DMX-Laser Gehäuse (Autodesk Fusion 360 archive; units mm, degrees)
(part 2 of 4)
sketch "Skizze2" plane through (0, 0, 5) normal (0, 0, 1) x axis (-1, 0, 0)
  line L1 (-37, -30) -> (-28, -30)
  line L2 (-40, -42) -> (-40, -33)
  line L3 (22, -45) -> (-37, -45)
  line L4 (25, 2) -> (25, -42)
  line L5 (-2, 5) -> (22, 5)
  line L6 (-5, 42) -> (-5, 8)
  line L7 (-22, 45) -> (-8, 45)
  line L8 (-25, -27) -> (-25, 42)
  line L9 (-20, -13) -> (-20, -45)
  line L10 (25, -13) -> (-25, -13)
  circle C1 centre (20, 0) radius 1.75
  circle C2 centre (20, -40) radius 1.75
  circle C3 centre (-20, 0) radius 1.75
  circle C4 centre (-10, 40) radius 1.75
  circle C5 centre (-20, 40) radius 1.75
  circle C6 centre (-35, -37.5) radius 1.75
  arc A1 centre (-37, -33) radius 3 clockwise from (-40, -33) to (-37, -30)
  arc A2 centre (-37, -42) radius 3 clockwise from (-37, -45) to (-40, -42)
  arc A3 centre (22, -42) radius 3 clockwise from (25, -42) to (22, -45)
  arc A4 centre (22, 2) radius 3 clockwise from (22, 5) to (25, 2)
  arc A5 centre (-2, 8) radius 3 clockwise from (-2, 5) to (-5, 8)
  arc A6 centre (-8, 42) radius 3 clockwise from (-8, 45) to (-5, 42)
  arc A7 centre (-22, 42) radius 3 clockwise from (-25, 42) to (-22, 45)
  arc A8 centre (-28, -27) radius 3 clockwise from (-25, -27) to (-28, -30)
  point P32 (-20, -45)
  point P34 (-25, -13)
  point P35 (25, -13)
  point P33 (-20, -13)
  coincident L3 P32
  perpendicular L3 L9
  coincident L8 P34
  coincident L4 P35
  perpendicular L4 L10
  dimension "d3" distance P32 P33 = 32
sketch "Skizze3" plane through (0, 0, 0) normal (0, 0, 1) x axis (1, 0, 0)
  line L1 (-25, 13) -> (25, 13)
  line L2 (-25, 23) -> (-25, 13)
  line L3 (25, 23) -> (-25, 23)
  line L4 (25, 13) -> (25, 23)
  line L5 (-25, 13) -> (25, 13)
  line L6 (-25, 3) -> (-25, 13)
  line L7 (25, 3) -> (-25, 3)
  line L8 (25, 13) -> (25, 3)
  point P2 (25, 13)
  point P3 (-25, 13)
  point P5 (25, 23)
  point P8 (25, 3)
  horizontal L1
  vertical L2
  horizontal L3
  vertical L4
  horizontal L5
  vertical L6
  horizontal L7
  vertical L8
  dimension "d4" distance P2 P3 = 50
  dimension "d5" distance P2 P5 = 10
  dimension "d6" distance P2 P8 = 10
sketch "Skizze4" plane through (0, 0, 5) normal (0, 0, 1) x axis (-1, 0, 0)
  line L1 (-37, -30) -> (-28, -30)
  line L2 (-40, -42) -> (-40, -33)
  line L3 (22, -45) -> (-37, -45)
  line L4 (25, 2) -> (25, -42)
  line L5 (-2, 5) -> (22, 5)
  line L6 (-5, 42) -> (-5, 8)
  line L7 (-22, 45) -> (-8, 45)
  line L8 (-25, -27) -> (-25, 42)
  line L9 (25, -3) -> (-25, -3)
  line L10 (25, -23) -> (25, -3)
  line L11 (-25, -23) -> (25, -23)
  line L12 (-25, -3) -> (-25, -23)
  line L13 (5, -3) -> (-25, -3)
  line L14 (5, -23) -> (5, -3)
  circle C1 centre (20, 0) radius 1.75
  circle C2 centre (20, -40) radius 1.75
  circle C3 centre (-20, 0) radius 1.75
  circle C4 centre (-10, 40) radius 1.75
  circle C5 centre (-20, 40) radius 1.75
  circle C6 centre (-35, -37.5) radius 1.75
  arc A1 centre (-37, -33) radius 3 clockwise from (-40, -33) to (-37, -30)
  arc A2 centre (-37, -42) radius 3 clockwise from (-37, -45) to (-40, -42)
  arc A3 centre (22, -42) radius 3 clockwise from (25, -42) to (22, -45)
  arc A4 centre (22, 2) radius 3 clockwise from (22, 5) to (25, 2)
  arc A5 centre (-2, 8) radius 3 clockwise from (-2, 5) to (-5, 8)
  arc A6 centre (-8, 42) radius 3 clockwise from (-8, 45) to (-5, 42)
  arc A7 centre (-22, 42) radius 3 clockwise from (-25, 42) to (-22, 45)
  arc A8 centre (-28, -27) radius 3 clockwise from (-25, -27) to (-28, -30)
  point P32 (-25, -3)
  point P37 (5, -23)
  point P35 (-25, -23)
  point P36 (5, -3)
  horizontal L9
  vertical L10
  horizontal L11
  vertical L12
  coincident L8 P32
  perpendicular L12 L13
  coincident L11 P37
  perpendicular L11 L14
  dimension "d7" distance P32 P35 = 20
  dimension "d8" distance P32 P36 = 30
extrude "Extrusion2" add sketch "Skizze4" profile of L8 L9 L11 L12 L13 L14 along normal blind 44.55
sketch "Skizze5" plane through (25, 0, 0) normal (1, 0, 0) x axis (0, 1, 0)
  line L1 (27, 0) -> (-42, 0)
  line L2 (27, 5) -> (27, 0)
  line L3 (23, 5) -> (27, 5)
  line L4 (23, 49.55) -> (23, 5)
  line L5 (3, 49.55) -> (23, 49.55)
  line L6 (3, 5) -> (3, 49.55)
  line L7 (-42, 5) -> (3, 5)
  line L8 (-42, 0) -> (-42, 5)
  line L9 (3, 39.55) -> (3, 5)
  line L10 (13, 39.55) -> (3, 39.55)
  line L11 (13, 37.7147) -> (3, 37.7147)
  circle C1 centre (13, 39.55) radius 2.5
  point P8 (3, 5)
  point P10 (3, 5)
  point P13 (3, 37.7147)
  point P12 (13, 39.55)
  point P15 (13, 39.55)
  point P11 (3, 39.55)
  coincident P8 P10
  perpendicular L7 L9
  perpendicular L6 L10
  coincident L6 P13
  perpendicular L6 L11
  coincident P12 P15
  dimension "d11" distance P10 P11 = 34.55
  dimension "d12" distance P11 P12 = 10
  dimension "d13" diameter C1 = 5
extrude "Extrusion3" cut sketch "Skizze5" profile of C1 against normal blind 50
extrude "Extrusion4" new body sketch "Skizze5" profile of L6 L9 L10 L11 C1 along normal blind 5
split "Teilen1"
sketch "Skizze6" plane through (0, 0, 5) normal (0, 0, 1) x axis (-1, 0, 0)
  line L1 (-25, -23) -> (5, -23)
  line L2 (-25, -27) -> (-25, -23)
  line L3 (-37, -30) -> (-28, -30)
  line L4 (-40, -42) -> (-40, -33)
  line L5 (22, -45) -> (-37, -45)
  line L6 (25, 2) -> (25, -42)
  line L7 (-2, 5) -> (22, 5)
  line L8 (-5, 42) -> (-5, 8)
  line L9 (-22, 45) -> (-8, 45)
  line L10 (-25, -3) -> (-25, 42)
  line L11 (5, -3) -> (-25, -3)
  line L12 (5, -23) -> (5, -3)
  arc A1 centre (-28, -27) radius 3 clockwise from (-25, -27) to (-28, -30)
  arc A2 centre (-37, -33) radius 3 clockwise from (-40, -33) to (-37, -30)
  arc A3 centre (-37, -42) radius 3 clockwise from (-37, -45) to (-40, -42)
  arc A4 centre (22, -42) radius 3 clockwise from (25, -42) to (22, -45)
  arc A5 centre (22, 2) radius 3 clockwise from (22, 5) to (25, 2)
  arc A6 centre (-2, 8) radius 3 clockwise from (-2, 5) to (-5, 8)
  arc A7 centre (-8, 42) radius 3 clockwise from (-8, 45) to (-5, 42)
  arc A8 centre (-22, 42) radius 3 clockwise from (-25, 42) to (-22, 45)
  circle C1 centre (20, 0) radius 1.75
  circle C2 centre (20, -40) radius 1.75
  circle C3 centre (-20, 0) radius 1.75
  circle C4 centre (-10, 40) radius 1.75
  circle C5 centre (-20, 40) radius 1.75
  circle C6 centre (-35, -37.5) radius 1.75
  circle C7 centre (-20, 0) radius 4.5
  concentric C3 C7
  dimension "d18" diameter C7 = 9
extrude "Extrusion5" cut sketch "Skizze6" profile of L11 C3 C7 along normal blind 5
fillet "Abrundung1" radius 5
fillet "Abrundung2" radius 5
sketch "Skizze7" plane through (0, 0, 49.55) normal (0, 0, 1) x axis (-1, 0, 0)
  line L1 (-25, -3) -> (5, -3)
  line L2 (-25, -23) -> (-25, -3)
  line L3 (5, -23) -> (-25, -23)
  line L4 (5, -3) -> (5, -23)
  line L5 (-25, -17) -> (-22, -17)
  line L6 (-1, -3) -> (-1, -6)
  line L7 (5, -9) -> (2, -9)
  circle C1 centre (-22, -20) radius 1.6
  circle C2 centre (-22, -20) radius 3
  circle C3 centre (2, -6) radius 1.6
  circle C4 centre (2, -6) radius 3
  point P10 (-22, -17)
  point P11 (-25, -17)
  point P12 (-1, -6)
  point P13 (-1, -3)
  point P14 (2, -9)
  point P15 (5, -9)
  concentric C1 C2
  concentric C3 C4
  tangent L4 C4
  coincident C2 P10
  coincident L2 P11
  tangent C2 L5
  perpendicular L2 L5
  coincident C4 P12
  coincident L1 P13
  perpendicular L1 L6
  coincident C4 P14
  coincident L4 P15
  perpendicular L4 L7
  dimension "d27" diameter C1 = 3.2
  dimension "d28" diameter C3 = 3.2
fillet "Abrundung3" radius 4
extrude "Extrusion6" cut sketch "Skizze7" profile of C1 C3 against normal blind 32
extrude "Extrusion7" cut sketch "Skizze7" profile of L1 L2 L3 L4 C1 C2 C3 C4 L5 L7 against normal blind 3
sketch "Skizze8" plane through (0, 0, 5) normal (0, 0, 1) x axis (-1, 0, 0)
  line L1 (-25.1716, -28) -> (5, -28)
  line L2 (-37, -30) -> (-28, -30)
  line L3 (-40, -42) -> (-40, -33)
  line L4 (22, -45) -> (-37, -45)
  line L5 (25, 2) -> (25, -42)
  line L6 (-2, 5) -> (22, 5)
  line L7 (-5, 42) -> (-5, 8)
  line L8 (-22, 45) -> (-8, 45)
  line L9 (-25, 2) -> (-25, 42)
  line L10 (-24.0311, 2) -> (-25, 2)
  line L11 (5, 2) -> (-15.9689, 2)
  line L12 (5, -28) -> (5, 2)
  line L13 (-10, 10) -> (-5, 10)
  line L14 (-12, 27) -> (-12, 12)
  line L15 (-5, 29) -> (-10, 29)
  arc A1 centre (-28, -27) radius 3 clockwise from (-25.1716, -28) to (-28, -30)
  arc A2 centre (-37, -33) radius 3 clockwise from (-40, -33) to (-37, -30)
  arc A3 centre (-37, -42) radius 3 clockwise from (-37, -45) to (-40, -42)
  arc A4 centre (22, -42) radius 3 clockwise from (25, -42) to (22, -45)
  arc A5 centre (22, 2) radius 3 clockwise from (22, 5) to (25, 2)
  arc A6 centre (-2, 8) radius 3 clockwise from (-2, 5) to (-5, 8)
  arc A7 centre (-8, 42) radius 3 clockwise from (-8, 45) to (-5, 42)
  arc A8 centre (-22, 42) radius 3 clockwise from (-25, 42) to (-22, 45)
  arc A9 centre (-20, 0) radius 4.5 clockwise from (-15.9689, 2) to (-24.0311, 2)
  circle C1 centre (20, 0) radius 1.75
  circle C2 centre (20, -40) radius 1.75
  circle C3 centre (-10, 40) radius 1.75
  circle C4 centre (-20, 40) radius 1.75
  circle C5 centre (-35, -37.5) radius 1.75
  circle C6 centre (-20, 0) radius 1.75
  arc A10 centre (-10, 12) radius 2 clockwise from (-10, 10) to (-12, 12)
  arc A11 centre (-10, 27) radius 2 clockwise from (-12, 27) to (-10, 29)
  point P37 (-5, 10)
  point P38 (-5, 29)
  coincident L7 P37
  perpendicular L7 L13
  perpendicular L13 L14
  coincident L7 P38
  perpendicular L7 L15
  tangent L13 A10
  tangent L14 A10
  tangent L14 A11
  tangent L15 A11
  equal A10 A11
  dimension "d33" radius A10 = 2
split "Teilen2"
split "Teilen3"
move "Verschieben2"
remove_body "Körper entfernen"
fillet "Abrundung4" radius 3
sketch "Skizze9" plane through (25, 0, 0) normal (1, 0, 0) x axis (0, 1, 0)
  line L1 (17, 46.55) -> (22.873, 46.55)
  line L2 (17, 49.55) -> (17, 46.55)
  line L3 (7, 49.55) -> (17, 49.55)
  line L4 (3, 39.55) -> (3, 45.55)
  line L5 (10.5, 39.55) -> (3, 39.55)
  line L6 (23, 39.55) -> (15.5, 39.55)
  line L7 (23, 45.55) -> (23, 39.55)
  arc A1 centre (7, 45.55) radius 4 clockwise from (3, 45.55) to (7, 49.55)
  arc A2 centre (13, 39.55) radius 2.5 clockwise from (10.5, 39.55) to (15.5, 39.55)
  arc A3 centre (19, 45.55) radius 4 clockwise from (22.873, 46.55) to (23, 45.55)
  circle C1 centre (13, 39.55) radius 5
  concentric A2 C1
  dimension "d38" diameter C1 = 10
extrude "Extrusion9" cut sketch "Skizze9" profile of L5 A2 L6 C1 against normal blind 200
split "Teilen4"
sketch "Skizze10" plane through (5, 0, 0) normal (-1, 0, 0) x axis (0, -1, 0)
  line L1 (5, 0) -> (-45, 0)
  line L2 (5, 5) -> (5, 0)
  line L3 (2, 5) -> (5, 5)
  line L4 (-3, 39.55) -> (-3, 10)
  line L5 (-8, 39.55) -> (-3, 39.55)
  line L6 (-23, 39.55) -> (-18, 39.55)
  line L7 (-23, 10) -> (-23, 39.55)
  line L8 (-45, 5) -> (-28, 5)
  line L9 (-45, 0) -> (-45, 5)
  arc A1 centre (2, 10) radius 5 clockwise from (2, 5) to (-3, 10)
  arc A2 centre (-13, 39.55) radius 5 clockwise from (-8, 39.55) to (-18, 39.55)
  arc A3 centre (-28, 10) radius 5 clockwise from (-23, 10) to (-28, 5)
  circle C1 centre (-13, 39.55) radius 6.5
  concentric A2 C1
  dimension "d41" diameter C1 = 13
extrude "Extrusion10" cut sketch "Skizze10" profile of L5 A2 L6 C1 against normal blind 5
combine "Kombinieren1"
combine "Kombinieren2"
sketch "Skizze11" plane through (-5, 0, 0) normal (-1, 0, 0) x axis (0, -1, 0)
  line L1 (-3, 39.55) -> (-8, 39.55)
  line L2 (-3, 45.55) -> (-3, 39.55)
  line L3 (-9, 46.55) -> (-3.127, 46.55)
  line L4 (-9, 49.55) -> (-9, 46.55)
  line L5 (-19, 49.55) -> (-9, 49.55)
  line L6 (-23, 39.55) -> (-23, 45.55)
  line L7 (-18, 39.55) -> (-23, 39.55)
  arc A1 centre (-13, 39.55) radius 5 clockwise from (-18, 39.55) to (-8, 39.55)
  arc A2 centre (-7, 45.55) radius 4 clockwise from (-3.127, 46.55) to (-3, 45.55)
  arc A3 centre (-19, 45.55) radius 4 clockwise from (-23, 45.55) to (-19, 49.55)
  circle C1 centre (-13, 39.55) radius 6.5
  concentric A1 C1
  dimension "d44" diameter C1 = 13
extrude "Extrusion11" cut sketch "Skizze11" profile of A1 L1 L7 C1 against normal blind 200
sketch "Skizze12" plane through (30, 0, 0) normal (1, 0, 0) x axis (0, 1, 0)
  line L1 (11.3025, 37.7147) -> (3, 37.7147)
  line L2 (3, 39.55) -> (10.5, 39.55)
  line L3 (3, 37.7147) -> (3, 39.55)
  line L4 (9.6, 37.7147) -> (9.6, 39.1)
  line L5 (9.6, 39.55) -> (9.6, 39.1)
  line L6 (9.6193, 39.7013) -> (9.6, 39.55)
  line L7 (10.5376, 39.7305) -> (9.6193, 39.7013)
  line L8 (11.5675, 37.69) -> (10.5376, 39.7305)
  line L9 (10.0244, 37.5274) -> (11.5675, 37.69)
  line L10 (9.6, 37.65) -> (10.0244, 37.5274)
  line L11 (9.6, 37.7147) -> (9.6, 37.65)
  arc A1 centre (13, 39.55) radius 2.5 clockwise from (11.3025, 37.7147) to (10.5, 39.55)
  point P8 (9.6, 37.7147)
  point P9 (9.6, 39.55)
  coincident L1 P8
  perpendicular L1 L4
  coincident L2 P9
  perpendicular L2 L5
  perpendicular L1 L11
extrude "Extrusion12" cut sketch "Skizze12" profile of L1 A1 L2 L4 L5 against normal blind 20
extrude "Extrusion13" cut of existing geometry blind -3.1
sketch "Skizze13" plane through (0, 0, 49.55) normal (0, 0, 1) x axis (-1, 0, 0)
  line L1 (-25, -7) -> (-0.8284, -7)
  line L2 (-25, -17) -> (-25, -7)
  line L3 (-22, -17) -> (-25, -17)
  line L4 (5, -19) -> (-19.1716, -19)
  line L5 (5, -9) -> (5, -19)
  line L6 (2, -9) -> (5, -9)
  line L7 (2, -25) -> (2, -6)
  line L8 (-22, -20) -> (2, -25)
  line L9 (4.4182, -20) -> (-22, -20)
  line L10 (5, -23) -> (2, -23)
  line L11 (5, -16) -> (5, -23)
  line L12 (5, -17) -> (2, -17)
  arc A1 centre (-22, -20) radius 3 clockwise from (-22, -17) to (-19.1716, -19)
  arc A2 centre (2, -6) radius 3 clockwise from (2, -9) to (-0.8284, -7)
  circle C1 centre (2, -20) radius 1.6
  circle C2 centre (2, -20) radius 3
  point P11 (2, -6)
  point P12 (2, -6)
  point P7 (-22, -20)
  point P14 (-22, -20)
  point P16 (2, -20)
  point P18 (2, -23)
  point P20 (5, -16)
  point P21 (2, -17)
  point P22 (5, -17)
  coincident P11 P12
  perpendicular L4 L7
  coincident P7 P14
  perpendicular L7 L9
  coincident L9 P16
  coincident L7 P16
  concentric C1 C2
  coincident C2 P18
  coincident L7 P18
  perpendicular L7 L10
  coincident L5 P20
  coincident C2 P21
  coincident L7 P21
  coincident L5 P22
  perpendicular L5 L12
  dimension "d51" diameter C1 = 3.2
  dimension "d52" diameter C2 = 6
extrude "Extrusion14" cut sketch "Skizze13" profile of L4 L5 L7 L9 C1 C2 L10 L11 L12 against normal blind 3
extrude "Extrusion15" cut sketch "Skizze13" profile of L4 L7 L9 C1 against normal blind 25
extrude "Extrusion16" cut of existing geometry blind -5
sketch "Skizze14" plane through (0, 3, 0) normal (0, -1, 0) x axis (1, 0, 0)
  line L1 (16.6459, 10) -> (-5, 10)
  line L2 (23.3541, 10) -> (16.6459, 10)
  line L3 (25, 10) -> (23.3541, 10)
  line L4 (25, 39.55) -> (25, 10)
  line L5 (-5, 39.55) -> (25, 39.55)
  line L6 (-5, 10) -> (-5, 39.55)
  line L7 (-5, 21) -> (-5, 46.5)
  line L8 (1, 24) -> (-5, 24)
  line L9 (-5, 24) -> (1, 24)
  line L10 (-5, 27.5) -> (-5, 24)
  line L11 (1, 27.5) -> (-5, 27.5)
  line L12 (1, 24) -> (1, 27.5)
  point P9 (-5, 21)
  point P10 (-5, 24)
  point P13 (-5, 27.5)
  point P11 (1, 24)
  coincident L6 P9
  coincident L6 P10
  perpendicular L6 L8
  horizontal L9
  vertical L10
  horizontal L11
  vertical L12
  coincident L6 P13
  dimension "d59" distance P10 P11 = 6
extrude "Extrusion17" cut sketch "Skizze14" profile of L6 L7 L8 L9 L10 L11 L12 against normal blind 24
sketch "Skizze15" plane through (0, 0, 24) normal (0, 0, 1) x axis (-1, 0, 0)
  line L1 (5, -23) -> (-1, -23)
  line L2 (5, -3) -> (5, -23)
  line L3 (-1, -3) -> (5, -3)
  line L4 (-1, -23) -> (-1, -3)
  line L5 (-1, -17) -> (5, -17)
  line L6 (-1, -9) -> (-1, -17)
  line L7 (5, -9) -> (-1, -9)
  line L8 (5, -17) -> (5, -9)
  circle C1 centre (2, -20) radius 1.6
  circle C2 centre (2, -6) radius 1.6
  point P8 (5, -17)
  point P9 (-1, -17)
  point P11 (5, -9)
  horizontal L5
  vertical L6
  horizontal L7
  vertical L8
  coincident L2 P8
  dimension "d62" distance P8 P9 = 6
  dimension "d63" distance P8 P11 = 8
extrude "Extrusion18" add sketch "Skizze15" profile of L2 L4 L5 L6 L7 L8 along normal blind 5
extrude "Extrusion19" add of existing geometry blind 33
extrude "Extrusion20" add of existing geometry blind 4
sketch "Skizze16" plane through (25, 0, 0) normal (1, 0, 0) x axis (0, 1, 0)
  line L1 (3, 10) -> (3, 45.55)
  line L2 (-2, 0) -> (-2, 5)
  line L3 (27, 0) -> (-2, 0)
  line L4 (27, 5.101) -> (27, 0)
  line L5 (23, 45.55) -> (23, 10)
  line L6 (22.873, 50.55) -> (22.873, 46.55)
  line L7 (17, 50.55) -> (22.873, 50.55)
  line L8 (17, 49.55) -> (17, 50.55)
  line L9 (7, 49.55) -> (17, 49.55)
  line L10 (22.873, 49.55) -> (15.6611, 49.55)
  line L11 (24.3811, 49.55) -> (22.873, 49.55)
  line L12 (23, 43) -> (24.3811, 49.55)
  line L13 (23, 49.55) -> (23, 43)
  line L14 (18.3587, 44.9087) -> (23, 49.55)
  arc A1 centre (-2, 10) radius 5 clockwise from (3, 10) to (-2, 5)
  arc A2 centre (28, 10) radius 5 clockwise from (27, 5.101) to (23, 10)
  arc A3 centre (19, 45.55) radius 4 clockwise from (22.873, 46.55) to (23, 45.55)
  arc A4 centre (7, 45.55) radius 4 clockwise from (3, 45.55) to (7, 49.55)
  circle C1 centre (13, 39.55) radius 6.5
  circle C2 centre (19, 45.55) radius 4
  point P20 (15.6611, 49.55)
  point P21 (22.873, 49.55)
  point P23 (23, 43)
  point P24 (23, 49.55)
  coincident L9 P20
  coincident L6 P21
  perpendicular L6 L10
  perpendicular L5 L11
  coincident L5 P23
  coincident L11 P24
  perpendicular L10 L13
  tangent L10 C2
  tangent L13 C2
  dimension "d70" angle L13 L14 = 45
  dimension "d71" radius C2 = 4
extrude "Extrusion21" cut sketch "Skizze16" profile of A3 L6 L7 L8 L10 L13 L14 C2 against normal blind 9
sketch "Skizze17" plane through (-5, 0, 0) normal (-1, 0, 0) x axis (0, -1, 0)
  line L1 (-3, 45.55) -> (-3, 27.5)
  line L2 (-9, 46.55) -> (-3.127, 46.55)
  line L3 (-9, 49.55) -> (-9, 46.55)
  line L4 (-17, 49.55) -> (-9, 49.55)
  line L5 (-17, 46.55) -> (-17, 49.55)
  line L6 (-22.873, 46.55) -> (-17, 46.55)
  line L7 (-23, 27.5) -> (-23, 45.55)
  line L8 (-17, 27.5) -> (-23, 27.5)
  line L9 (-17, 24) -> (-17, 27.5)
  line L10 (-23, 24) -> (-17, 24)
  line L11 (-23, 10) -> (-23, 24)
  line L12 (2, 5) -> (-28, 5)
  line L13 (-3, 24) -> (-3, 10)
  line L14 (-9, 24) -> (-3, 24)
  line L15 (-9, 27.5) -> (-9, 24)
  line L16 (-3, 27.5) -> (-9, 27.5)
  circle C1 centre (-13, 39.55) radius 6.5
  arc A1 centre (-7, 45.55) radius 4 clockwise from (-3.127, 46.55) to (-3, 45.55)
  arc A2 centre (-19, 45.55) radius 4 clockwise from (-23, 45.55) to (-22.873, 46.55)
  arc A3 centre (-28, 10) radius 5 clockwise from (-23, 10) to (-28, 5)
  arc A4 centre (2, 10) radius 5 clockwise from (2, 5) to (-3, 10)
  circle C2 centre (-13, 39.55) radius 6.5
  concentric C1 C2
extrude "Extrusion22" cut sketch "Skizze17" profile of C1 C2 against normal blind 300
split "Teilen5"
sketch "Skizze18" plane through (25, 0, 0) normal (1, 0, 0) x axis (0, 1, 0)
  line L1 (19.5, 39.55) -> (23, 39.55)
  line L2 (3, 39.55) -> (6.5, 39.55)
  line L3 (3, 10) -> (3, 39.55)
  line L4 (-2, 0) -> (-2, 5)
  line L5 (27, 0) -> (-2, 0)
  line L6 (27, 5.101) -> (27, 0)
  line L7 (23, 39.55) -> (23, 10)
  arc A1 centre (13, 39.55) radius 6.5 clockwise from (19.5, 39.55) to (6.5, 39.55)
  arc A2 centre (-2, 10) radius 5 clockwise from (3, 10) to (-2, 5)
  arc A3 centre (28, 10) radius 5 clockwise from (27, 5.101) to (23, 10)
  circle C1 centre (13, 39.55) radius 6.85
  concentric A1 C1
  dimension "d76" diameter C1 = 13.7
extrude "Extrusion23" cut sketch "Skizze18" profile of L1 A1 L2 C1 against normal blind 300
sketch "Skizze19" plane through (25, 0, 0) normal (1, 0, 0) x axis (0, 1, 0)
  line L1 (23, 39.55) -> (19.85, 39.55)
  line L2 (23, 45.55) -> (23, 39.55)
  line L3 (7, 49.55) -> (19, 49.55)
  line L4 (3, 39.55) -> (3, 45.55)
  line L5 (6.15, 39.55) -> (3, 39.55)
  arc A1 centre (13, 39.55) radius 6.85 clockwise from (6.15, 39.55) to (19.85, 39.55)
  arc A2 centre (19, 45.55) radius 4 clockwise from (22.873, 46.55) to (23, 45.55)
  arc A3 centre (19, 45.55) radius 4 clockwise from (19, 49.55) to (22.873, 46.55)
  arc A4 centre (7, 45.55) radius 4 clockwise from (3, 45.55) to (7, 49.55)
  circle C1 centre (13, 39.55) radius 7.25
  concentric A1 C1
  dimension "d79" diameter C1 = 14.5
extrude "Extrusion24" cut sketch "Skizze19" profile of A1 L1 L5 C1 against normal blind 3000
split "Teilen6"
move "Verschieben3"
combine "Kombinieren3"
extrude "Extrusion8" cut sketch "Skizze8" profile of L7 L13 L14 L15 A10 A11 against normal blind 3

design "Spiegelaufbau"
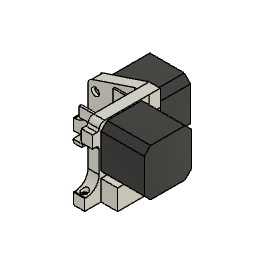
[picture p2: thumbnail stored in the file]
sketch "Skizze1" plane through (0, 0, 0) normal (0, 0, 1) x axis (1, 0, 0)
  line L1 (42.3, 0) -> (0, 0)
  line L2 (42.3, 42.3) -> (42.3, 0)
  line L3 (0, 42.3) -> (42.3, 42.3)
  line L4 (0, 0) -> (0, 42.3)
  line L5 (5.65, 42.3) -> (0, 42.3)
  line L6 (5.65, 36.65) -> (5.65, 42.3)
  line L7 (0, 36.65) -> (5.65, 36.65)
  line L8 (0, 42.3) -> (0, 36.65)
  line L9 (36.65, 36.65) -> (5.65, 36.65)
  line L10 (36.65, 5.65) -> (36.65, 36.65)
  line L11 (5.65, 5.65) -> (36.65, 5.65)
  line L12 (5.65, 36.65) -> (5.65, 5.65)
  line L13 (0, 36.65) -> (5.65, 42.3)
  line L14 (5.65, 0) -> (0, 5.65)
  line L15 (36.65, 0) -> (42.3, 5.65)
  line L16 (42.3, 36.65) -> (36.65, 42.3)
  point P1 (0, 0)
  point P2 (0, 0)
  point P12 (0, 5.65)
  point P13 (5.65, 0)
  point P14 (42.3, 5.65)
  point P15 (36.65, 0)
  point P16 (36.65, 42.3)
  point P17 (42.3, 36.65)
  point P3 (42.3, 0)
  point P5 (0, 42.3)
  point P6 (5.65, 42.3)
  point P8 (0, 36.65)
  point P7 (5.65, 36.65)
  point P9 (36.65, 36.65)
  point P11 (5.65, 5.65)
  horizontal L1
  vertical L2
  horizontal L3
  vertical L4
  coincident P1 P2
  horizontal L5
  vertical L6
  horizontal L7
  vertical L8
  horizontal L9
  vertical L10
  horizontal L11
  vertical L12
  coincident L4 P12
  coincident L1 P13
  perpendicular L13 L14
  coincident L2 P14
  coincident L1 P15
  perpendicular L14 L15
  coincident L3 P16
  coincident L2 P17
  perpendicular L15 L16
  dimension "d1" distance P2 P3 = 42.3
  dimension "d2" distance P2 P5 = 42.3
  dimension "d3" distance P5 P6 = 5.65
  dimension "d4" distance P5 P8 = 5.65
  dimension "d5" distance P7 P9 = 31
  dimension "d6" distance P7 P11 = 31
extrude "Extrusion1" new body sketch "Skizze1" profile of L1 L2 L3 L4 L6 L7 L9 L10 L11 L12 L13 L14 L15 L16 along normal blind 39 bodies "Nema 17-39"
sketch "Skizze2" plane through (0, 0, 0) normal (0, 0, 1) x axis (1, 0, 0)
  line L1 (42.3, 0) -> (0, 0)
  line L2 (42.3, 42.3) -> (42.3, 0)
  line L3 (0, 42.3) -> (42.3, 42.3)
  line L4 (0, 0) -> (0, 42.3)
  line L5 (5.65, 42.3) -> (0, 42.3)
  line L6 (5.65, 38.65) -> (5.65, 42.3)
  line L7 (0, 36.65) -> (3.65, 36.65)
  line L8 (0, 42.3) -> (0, 36.65)
  line L9 (36.65, 36.65) -> (7.65, 36.65)
  line L10 (36.65, 7.65) -> (36.65, 34.65)
  line L11 (7.65, 5.65) -> (34.65, 5.65)
  line L12 (5.65, 36.65) -> (5.65, 7.65)
  line L13 (35.2358, 35.2358) -> (7.0642, 7.0642)
  line L14 (7.0642, 35.2358) -> (36.65, 5.65)
  circle C1 centre (5.65, 5.65) radius 2
  circle C2 centre (36.65, 5.65) radius 2
  circle C3 centre (5.65, 36.65) radius 2
  circle C4 centre (36.65, 36.65) radius 2
  circle C5 centre (21.15, 21.15) radius 2.5
  point P1 (0, 0)
  point P2 (0, 0)
  point P10 (36.65, 5.65)
  point P12 (36.65, 5.65)
  point P7 (5.65, 36.65)
  point P13 (5.65, 36.65)
  point P9 (36.65, 36.65)
  point P14 (36.65, 36.65)
  point P16 (7.65, 5.65)
  point P17 (7.0642, 7.0642)
  point P18 (5.65, 7.65)
  point P19 (34.65, 5.65)
  point P20 (36.65, 7.65)
  point P21 (36.65, 34.65)
  point P22 (35.2358, 35.2358)
  point P23 (7.65, 36.65)
  point P24 (7.0642, 35.2358)
  point P15 (21.15, 21.15)
  point P25 (5.65, 38.65)
  point P26 (3.65, 36.65)
  point P3 (42.3, 0)
  point P5 (0, 42.3)
  point P6 (5.65, 42.3)
  point P8 (0, 36.65)
  point P11 (5.65, 5.65)
  horizontal L1
  vertical L2
  horizontal L3
  vertical L4
  coincident P1 P2
  horizontal L5
  vertical L6
  horizontal L7
  vertical L8
  horizontal L9
  vertical L10
  horizontal L11
  vertical L12
  coincident P10 P12
  coincident P7 P13
  coincident P9 P14
  coincident C1 P16
  coincident C1 P17
  coincident C1 P18
  coincident C2 P19
  coincident C2 P20
  coincident C4 P21
  coincident C4 P22
  coincident C3 P23
  coincident C3 P24
  coincident L14 P15
  coincident C3 P25
  coincident C3 P26
  dimension "d9" distance P2 P3 = 42.3
  dimension "d10" distance P2 P5 = 42.3
  dimension "d11" distance P5 P6 = 5.65
  dimension "d12" distance P5 P8 = 5.65
  dimension "d13" distance P7 P9 = 31
  dimension "d14" distance P7 P11 = 31
  dimension "d15" diameter C1 = 4
  dimension "d16" diameter C2 = 4
  dimension "d17" diameter C3 = 4
  dimension "d18" diameter C4 = 4
  dimension "d19" diameter C5 = 5
extrude "Extrusion2" cut sketch "Skizze2" profile of C1 C2 C3 C4 along normal blind 6
extrude "Extrusion3" add sketch "Skizze2" profile of L13 L14 C5 against normal blind 24
move "Verschieben1"
sketch "Skizze3" plane through (0, 0, 0) normal (0, 1, 0) x axis (1, 0, 0)
  line L1 (55, 0) -> (0, 0)
  line L2 (55, -45) -> (55, 0)
  line L3 (0, -45) -> (55, -45)
  line L4 (0, 0) -> (0, -45)
  point P1 (0, 0)
  point P2 (0, 0)
  horizontal L1
  vertical L2
  horizontal L3
  vertical L4
  coincident P1 P2
extrude "Extrusion4" new body sketch "Skizze3" along normal blind 10
sketch "Skizze4" plane through (0, 10, 0) normal (0, 1, 0) x axis (-1, 0, 0)
  line L1 (-55, 45) -> (0, 45)
  line L2 (-55, 0) -> (-55, 45)
  line L3 (0, 0) -> (-55, 0)
  line L4 (0, 45) -> (0, 0)
  line L5 (-45, 45) -> (-55, 45)
  line L6 (-45, 0) -> (-45, 45)
  line L7 (-55, 0) -> (-45, 0)
  line L8 (-55, 45) -> (-55, 0)
  point P8 (-45, 0)
  point P3 (-55, 45)
  point P6 (-55, 45)
  horizontal L5
  vertical L6
  horizontal L7
  vertical L8
  coincident L3 P8
  coincident P3 P6
extrude "Extrusion5" add sketch "Skizze4" profile of L1 L2 L3 L5 L6 L7 L8 along normal blind 45
move "Verschieben2"
extrude "Extrusion6" cut of existing geometry blind 77
sketch "Skizze5" plane through (0, 0, 0) normal (0, -1, 0) x axis (1, 0, 0)
  line L1 (0, 45) -> (55, 45)
  line L2 (0, 0) -> (0, 45)
  line L3 (55, 0) -> (0, 0)
  line L4 (55, 45) -> (55, 0)
  line L5 (37.65, 7.05) -> (6.65, 38.05)
  line L6 (6.65, 7.05) -> (37.65, 38.05)
  circle C1 centre (6.65, 7.05) radius 2
  circle C2 centre (37.65, 38.05) radius 2
  circle C3 centre (6.65, 38.05) radius 2
  circle C4 centre (37.65, 7.05) radius 2
  circle C5 centre (22.15, 22.55) radius 11.025
  point P4 (6.65, 38.05)
  point P10 (6.65, 38.05)
  point P5 (37.65, 7.05)
  point P11 (37.65, 7.05)
  point P3 (37.65, 38.05)
  point P12 (37.65, 38.05)
  point P2 (6.65, 7.05)
  point P13 (6.65, 7.05)
  point P14 (22.15, 22.55)
  coincident P4 P10
  coincident P5 P11
  coincident P3 P12
  coincident P2 P13
  midpoint L6 P14
  dimension "d30" diameter C5 = 22.05
extrude "Extrusion7" cut sketch "Skizze5" profile of L5 L6 C5 against normal blind 10
sketch "Skizze6" plane through (0, 0, 45) normal (0, 0, 1) x axis (-1, 0, 0)
  line L1 (-55, 0) -> (0, 0)
  line L2 (-55, -55) -> (-55, 0)
  line L3 (-45, -55) -> (-55, -55)
  line L4 (-45, -10) -> (-45, -55)
  line L5 (0, -10) -> (-45, -10)
  line L6 (0, 0) -> (0, -10)
  line L7 (-55, -10) -> (-45, -10)
  point P6 (-45, -10)
  point P8 (-45, -10)
  point P9 (-55, -10)
  coincident P6 P8
  coincident L2 P9
  perpendicular L2 L7
extrude "Extrusion8" cut sketch "Skizze6" profile of L2 L3 L4 L7 against normal blind 50
move "Verschieben3"
copy_paste_bodies "Körper kopieren/einfügen2"
move "Verschieben4"
sketch "Skizze7" plane through (0, 0, 45) normal (0, 0, 1) x axis (-1, 0, 0)
  line L1 (-55, 0) -> (-55, 55)
  line L2 (-45, 0) -> (-55, 0)
  line L3 (-45, 55) -> (-45, 0)
  line L4 (-55, 55) -> (-45, 55)
  line L5 (-45, 55) -> (-55, 55)
  line L6 (-45, 45) -> (-45, 55)
  line L7 (-55, 45) -> (-45, 45)
  line L8 (-55, 55) -> (-55, 45)
  point P8 (-45, 45)
  point P2 (-55, 55)
  point P6 (-55, 55)
  horizontal L5
  vertical L6
  horizontal L7
  vertical L8
  coincident L3 P8
  coincident P2 P6
extrude "Extrusion9" cut sketch "Skizze7" profile of L1 L3 L4 L5 L6 L7 L8 against normal blind 50
move "Verschieben5"
extrude "Extrusion10" add of existing geometry blind 15
sketch "Skizze8" plane through (0, 0, 0) normal (0, 1, 0) x axis (-1, 0, 0)
  line L1 (-45, 45) -> (-55, 45)
  line L2 (-45, 60) -> (-45, 45)
  line L3 (-55, 60) -> (-45, 60)
  line L4 (-55, 45) -> (-55, 60)
  line L5 (0, 45) -> (-45, 60)
  line L6 (-45, 45) -> (-45, 60)
  line L7 (0, 45) -> (-45, 45)
  point P4 (-45, 60)
  point P6 (-45, 60)
  point P8 (-45, 60)
  point P3 (-45, 45)
  point P9 (-45, 45)
  coincident P4 P6
  coincident P4 P8
  coincident P3 P9
  perpendicular L2 L7
extrude "Extrusion11" add sketch "Skizze8" along normal blind 10
sketch "Skizze9" plane through (45, 0, 0) normal (-1, 0, 0) x axis (0, -1, 0)
  dimension "d41" = 4
extrude "Extrusion12" cut sketch "Skizze9" against normal blind 1
sketch "Skizze10" plane through (0, 0, 0) normal (0, 0, -1) x axis (1, 0, 0)
  line L1 (55, -10) -> (0, -10)
  line L2 (55, 45) -> (55, -10)
  line L3 (45, 45) -> (55, 45)
  line L4 (45, 0) -> (45, 45)
  line L5 (0, 0) -> (45, 0)
  line L6 (0, -10) -> (0, 0)
  line L7 (51.4645, -13.5355) -> (41.4645, -3.5355)
  line L8 (64.4645, -26.5355) -> (51.4645, -13.5355)
  line L9 (58.5355, -6.4645) -> (48.5355, 3.5355)
  line L10 (71.5355, -19.4645) -> (58.5355, -6.4645)
  line L11 (64.4645, -26.5355) -> (71.5355, -19.4645)
  line L12 (48.5355, 3.5355) -> (41.4645, -3.5355)
  line L13 (-13, -10) -> (0, -10)
  line L14 (-13, 0) -> (-13, -10)
  line L15 (0, 0) -> (-13, 0)
  line L16 (0, -10) -> (0, 0)
  line L17 (45, 45) -> (55, 45)
  line L18 (45, 58) -> (45, 45)
  line L19 (55, 58) -> (45, 58)
  line L20 (55, 45) -> (55, 58)
  point P2 (0, -10)
  point P14 (0, -10)
  point P4 (55, 45)
  point P18 (55, 45)
  perpendicular L8 L11
  perpendicular L9 L12
  horizontal L13
  vertical L14
  horizontal L15
  vertical L16
  coincident P2 P14
  horizontal L17
  vertical L18
  horizontal L19
  vertical L20
  coincident P4 P18
extrude "Extrusion13" add sketch "Skizze10" profile of L1 L2 L3 L6 L7 L8 L9 L10 L11 L13 L14 L15 L16 L17 L18 L19 L20 against normal blind 8
fillet "Abrundung1" radius 12
sketch "Skizze11" plane through (0, 0, 60) normal (0, 0, 1) x axis (-1, 0, 0)
  line L1 (-55, 45) -> (-45, 45)
  line L2 (-55, 0) -> (-55, 45)
  line L3 (-55, -10) -> (-55, 0)
  line L4 (-45, -10) -> (-55, -10)
  line L5 (-45, 0) -> (-45, -10)
  line L6 (-45, 45) -> (-45, 0)
  line L7 (-64.4643, -26.536) -> (-71.5357, -19.4647)
  line L8 (-64.4645, -19.4648) -> (-68, -23.0003)
  circle C1 centre (-50, 53) radius 1.75
  circle C2 centre (8, -5) radius 1.75
  circle C3 centre (-64.4645, -19.4648) radius 1.75
  point P12 (-68, -23.0003)
  point P13 (-64.4645, -19.4648)
  point P14 (-64.4645, -19.4648)
  midpoint L7 P12
  perpendicular L7 L8
  coincident P13 P14
  dimension "d50" diameter C1 = 3.5
  dimension "d51" diameter C2 = 3.5
  dimension "d52" distance P12 P13 = 5
  dimension "d53" diameter C3 = 3.5
extrude "Extrusion14" cut sketch "Skizze11" profile of C1 C2 C3 against normal blind 95
sketch "Skizze12" plane through (0, 0, 60) normal (0, 0, 1) x axis (-1, 0, 0)
  circle C1 centre (-50, 53) radius 3
  circle C2 centre (8, -5) radius 3
  circle C3 centre (-64.4647, -19.4654) radius 3
  dimension "d56" diameter C1 = 6
  dimension "d57" diameter C2 = 6
  dimension "d58" diameter C3 = 6
extrude "Extrusion15" cut sketch "Skizze12" against normal blind 54
extrude "Extrusion16" add of existing geometry blind 2
sketch "Skizze13" plane through (0, 10, 0) normal (0, 1, 0) x axis (-1, 0, 0)
  line L1 (-47.9289, 20) -> (-55, 20)
  line L2 (-47.9289, 8) -> (-47.9289, 20)
  line L3 (-47.9289, -2) -> (-47.9289, 8)
  line L4 (13, -2) -> (-47.9289, -2)
  line L5 (13, 8) -> (13, -2)
  line L6 (12, 8) -> (13, 8)
  line L7 (0, 45) -> (0, 20)
  line L8 (-45, 60) -> (0, 45)
  line L9 (-55, 60) -> (-45, 60)
  line L10 (-55, 45) -> (-55, 60)
  line L11 (-55, 20) -> (-55, 45)
  line L12 (-1, 1.4) -> (-11, 1.4)
  line L13 (-43.3622, 1.4) -> (-11, 1.4)
  line L14 (-43.3622, -2) -> (-43.3622, 1.4)
  line L15 (-1, 1.4) -> (-43.3622, 1.4)
  line L16 (-1, -2) -> (-1, 1.4)
  line L17 (-43.3622, -2) -> (-1, -2)
  line L18 (-43.3622, 1.4) -> (-43.3622, -2)
  circle C1 centre (-37.65, 7.05) radius 2
  circle C2 centre (-6.65, 38.05) radius 2
  circle C3 centre (-37.65, 38.05) radius 2
  circle C4 centre (-6.65, 7.05) radius 2
  circle C5 centre (-22.15, 22.55) radius 11.025
  arc A1 centre (12, 20) radius 12 clockwise from (12, 8) to (0, 20)
  point P23 (-43.3622, -2)
  point P25 (-1, -2)
  parallel L4 L12
  parallel L12 L13
  coincident L4 P23
  perpendicular L4 L14
  horizontal L15
  vertical L16
  horizontal L17
  vertical L18
  coincident L4 P25
extrude "Extrusion17" add sketch "Skizze13" profile of L4 L12 L13 L14 L15 L16 L17 L18 along normal blind 10
sketch "Skizze14" plane through (55, 0, 0) normal (1, 0, 0) x axis (0, 1, 0)
  line L1 (2.9289, 20) -> (2.9289, 8)
  line L2 (10, 20) -> (2.9289, 20)
  line L3 (10, 45) -> (10, 20)
  line L4 (0, 45) -> (10, 45)
  line L5 (0, 60) -> (0, 45)
  line L6 (-45, 60) -> (0, 60)
  line L7 (-45, 20) -> (-45, 60)
  line L8 (-58, 8) -> (-57, 8)
  line L9 (-58, -2) -> (-58, 8)
  line L10 (2.9289, -2) -> (-58, -2)
  line L11 (2.9289, 8) -> (2.9289, -2)
  line L12 (-1, 16.4) -> (-25, 16.4)
  line L13 (-43.3405, 16.4) -> (-1, 16.4)
  line L14 (-1, 16.4) -> (-43.3405, 16.4)
  line L15 (-1, 13) -> (-1, 16.4)
  line L16 (-43.3405, 13) -> (-1, 13)
  line L17 (-43.3405, 16.4) -> (-43.3405, 13)
  circle C1 centre (-22.15, 37.55) radius 11.025
  circle C2 centre (-6.65, 22.05) radius 2
  circle C3 centre (-37.65, 53.05) radius 2
  circle C4 centre (-6.65, 53.05) radius 2
  circle C5 centre (-37.65, 22.05) radius 2
  arc A1 centre (-57, 20) radius 12 clockwise from (-45, 20) to (-57, 8)
  point P22 (-43.3405, 16.4)
  point P25 (-43.3405, 13)
  perpendicular L7 L12
  perpendicular L7 L13
  horizontal L14
  vertical L15
  horizontal L16
  vertical L17
  dimension "d65" distance P22 P25 = 3.4
extrude "Extrusion18" add sketch "Skizze14" profile of L12 L13 L14 L15 L16 L17 along normal blind 10
fillet "Abrundung2" radius 5
fillet "Abrundung3" radius 5
fillet "Abrundung4" radius 3
fillet "Abrundung5" radius 5
extrude "Extrusion20" add of existing geometry blind 5
extrude "Extrusion21" add of existing geometry blind 5
delete_face "Fläche löschen1"
extrude "Extrusion22" add of existing geometry blind 15
sketch "Skizze15" plane through (55, 0, 0) normal (1, 0, 0) x axis (0, 1, 0)
  line L1 (-1, -2) -> (-1, 16.4)
  line L2 (0.8579, -2) -> (-1, -2)
  line L3 (0.8579, 8) -> (0.8579, -2)
  line L4 (0.8579, 20) -> (0.8579, 8)
  line L5 (10, 20) -> (0.8579, 20)
  line L6 (10, 45) -> (10, 20)
  line L7 (0, 45) -> (10, 45)
  line L8 (0, 60) -> (0, 45)
  line L9 (-40, 60) -> (0, 60)
  line L10 (-45, 20) -> (-45, 55)
  line L11 (-58, 8) -> (-57, 8)
  line L12 (-58, -2) -> (-58, 8)
  line L13 (-43.3405, -2) -> (-58, -2)
  line L14 (-43.3405, 16.4) -> (-43.3405, -2)
  line L15 (-1, 16.4) -> (-43.3405, 16.4)
  line L16 (0.8579, 30) -> (-1, 30)
  line L17 (0.8579, -2) -> (0.8579, 30)
  line L18 (-1, -2) -> (0.8579, -2)
  line L19 (-1, 30) -> (-1, -2)
  arc A1 centre (-40, 55) radius 5 clockwise from (-45, 55) to (-40, 60)
  arc A2 centre (-57, 20) radius 12 clockwise from (-45, 20) to (-57, 8)
  circle C1 centre (-37.65, 22.05) radius 2
  circle C2 centre (-6.65, 53.05) radius 2
  circle C3 centre (-37.65, 53.05) radius 2
  circle C4 centre (-6.65, 22.05) radius 2
  circle C5 centre (-22.15, 37.55) radius 11.025
  point P4 (0.8579, -2)
  point P28 (0.8579, -2)
  horizontal L16
  vertical L17
  horizontal L18
  vertical L19
  coincident P4 P28
extrude "Extrusion23" add sketch "Skizze15" profile of L1 L2 L3 L4 L16 L17 L18 L19 along normal blind 5
sketch "Skizze16" plane through (0, 10, 0) normal (0, 1, 0) x axis (-1, 0, 0)
  line L1 (-45, 60) -> (-3.4189, 46.1396)
  line L2 (-55, 60) -> (-45, 60)
  line L3 (-55, 45) -> (-55, 60)
  line L4 (-55, 20) -> (-55, 45)
  line L5 (-45.8579, 20) -> (-55, 20)
  line L6 (-45.8579, 8) -> (-45.8579, 20)
  line L7 (-45.8579, -2) -> (-45.8579, 8)
  line L8 (-43.3622, -2) -> (-45.8579, -2)
  line L9 (-43.3622, 1.4) -> (-43.3622, -2)
  line L10 (-1, 1.4) -> (-43.3622, 1.4)
  line L11 (-1, -2) -> (-1, 1.4)
  line L12 (13, -2) -> (-1, -2)
  line L13 (13, 8) -> (13, -2)
  line L14 (12, 8) -> (13, 8)
  line L15 (0, 41.3962) -> (0, 20)
  line L16 (-45.18, 30) -> (-43.3, 30)
  line L17 (-45.18, -2) -> (-45.18, 30)
  line L18 (-43.3, -2) -> (-45.18, -2)
  line L19 (-43.3, 30) -> (-43.3, -2)
  circle C1 centre (-22.15, 22.55) radius 11.025
  circle C2 centre (-6.65, 7.05) radius 2
  circle C3 centre (-37.65, 38.05) radius 2
  circle C4 centre (-6.65, 38.05) radius 2
  circle C5 centre (-37.65, 7.05) radius 2
  arc A1 centre (-5, 41.3962) radius 5 clockwise from (-3.4189, 46.1396) to (0, 41.3962)
  arc A2 centre (12, 20) radius 12 clockwise from (12, 8) to (0, 20)
  point P28 (-45.18, -2)
  point P26 (-43.3, 30)
  point P27 (-45.18, 30)
  horizontal L16
  vertical L17
  horizontal L18
  vertical L19
  coincident L8 P28
  dimension "d86" distance P26 P27 = 1.88
extrude "Extrusion24" add sketch "Skizze16" profile of L8 L9 L10 L16 L17 L18 L19 along normal blind 5
fillet "Abrundung6" radius 5
sketch "Skizze17" plane through (0, 0, 60) normal (0, 0, 1) x axis (-1, 0, 0)
  line L1 (-55, 40) -> (-45, 40)
  line L2 (-55, 0) -> (-55, 40)
  line L3 (-55, -10) -> (-55, 0)
  line L4 (-45, -10) -> (-55, -10)
  line L5 (-45, 3) -> (-45, -10)
  line L6 (-45, 40) -> (-45, 3)
  line L7 (-18.662, 19.65) -> (-45, 19.65)
  line L8 (-18.662, 24.65) -> (-18.662, 19.65)
  line L9 (-45, 24.65) -> (-18.662, 24.65)
  line L10 (-45, 19.65) -> (-45, 24.65)
  line L11 (-19.65, 0) -> (-24.65, 0)
  line L12 (-19.65, 26.5933) -> (-19.65, 0)
  line L13 (-24.65, 26.5933) -> (-19.65, 26.5933)
  line L14 (-24.65, 0) -> (-24.65, 26.5933)
  line L15 (-31, 24.65) -> (-31, 19.65)
  line L16 (-19.65, 14) -> (-24.65, 14)
  line L17 (-24.65, 14) -> (-24.65, 19.65)
  line L18 (-24.65, 19.65) -> (-31, 19.65)
  point P8 (-45, 19.65)
  point P16 (-31, 19.65)
  point P17 (-31, 24.65)
  point P18 (-24.65, 14)
  point P19 (-19.65, 14)
  point P20 (-24.65, 19.65)
  point P11 (-45, 24.65)
  point P12 (-24.65, 0)
  point P13 (-19.65, 0)
  horizontal L7
  vertical L8
  horizontal L9
  vertical L10
  coincident L6 P8
  horizontal L11
  vertical L12
  horizontal L13
  vertical L14
  coincident L7 P16
  coincident L9 P17
  perpendicular L9 L15
  coincident L14 P18
  coincident L12 P19
  perpendicular L12 L16
  coincident L7 P20
  coincident L14 P20
  dimension "d91" distance P8 P11 = 5
  dimension "d92" distance P12 P13 = 5
sketch "Skizze18" plane through (0, -45, 0) normal (0, -1, 0) x axis (1, 0, 0)
  line L1 (45, 55) -> (55, 55)
  line L2 (45, 20) -> (45, 55)
  line L3 (55, 20) -> (45, 20)
  line L4 (55, 55) -> (55, 20)
  line L5 (16.1247, 40.05) -> (45, 40.05)
  line L6 (16.1247, 35.05) -> (16.1247, 40.05)
  line L7 (45, 35.05) -> (16.1247, 35.05)
  line L8 (45, 40.05) -> (45, 35.05)
  line L9 (24.65, 22.55) -> (19.65, 22.55)
  line L10 (24.65, 43.1725) -> (24.65, 22.55)
  line L11 (19.65, 43.1725) -> (24.65, 43.1725)
  line L12 (19.65, 22.55) -> (19.65, 43.1725)
  line L13 (24.65, 22.55) -> (24.65, 35.05)
  line L14 (24.65, 37.55) -> (24.65, 35.05)
  point P6 (45, 40.05)
  point P14 (24.65, 35.05)
  point P9 (45, 35.05)
  point P10 (19.65, 22.55)
  point P11 (24.65, 22.55)
  point P15 (24.65, 37.55)
  horizontal L5
  vertical L6
  horizontal L7
  vertical L8
  coincident L2 P6
  horizontal L9
  vertical L10
  horizontal L11
  vertical L12
  coincident L10 P14
  coincident L7 P14
  perpendicular L7 L14
  dimension "d93" distance P6 P9 = 5
  dimension "d94" distance P10 P11 = 5
  dimension "d95" distance P14 P15 = 2.5
extrude "Extrusion25" add sketch "Skizze9" against normal blind 2
sketch "Skizze19" plane through (45, 0, 0) normal (-1, 0, 0) x axis (0, -1, 0)
  line L1 (3, 60) -> (40, 60)
  line L2 (3, -2) -> (3, 60)
  line L3 (58, -2) -> (3, -2)
  line L4 (58, 8) -> (58, -2)
  line L5 (57, 8) -> (58, 8)
  line L6 (45, 55) -> (45, 20)
  curve K1
  curve K2
  curve K3
  curve K4
  arc A1 centre (40, 55) radius 5 clockwise from (40, 60) to (45, 55)
  arc A2 centre (57, 20) radius 12 clockwise from (57, 8) to (45, 20)
  circle C1 centre (22.15, 37.55) radius 11.025
  circle C2 centre (6.65, 22.05) radius 2
  circle C3 centre (37.65, 53.05) radius 2
  circle C4 centre (6.65, 53.05) radius 2
  circle C5 centre (37.65, 22.05) radius 2
  dimension "d98" Text1-Height = 4
extrude "Extrusion26" cut sketch "Skizze19" against normal blind 2
sketch "Skizze20" plane through (31, 0, 0) normal (-1, 0, 0) x axis (0, -1, 0)
  circle C1 centre (22.15, 37.55) radius 2.5
  circle C2 centre (22.15, 37.55) radius 2.5
  circle C3 centre (22.15, 37.55) radius 4.5
  concentric C1 C2
  concentric C2 C3
  dimension "d101" diameter C3 = 9
extrude "Extrusion27" new body sketch "Skizze20" along normal blind 2
extrude "Extrusion28" new body of existing geometry blind 12
combine "Kombinieren1"
sketch "Skizze21" plane through (29, 0, 0) normal (-1, 0, 0) x axis (0, -1, 0)
  line L1 (22.15, 32.55) -> (22.15, 42.55)
  circle C1 centre (22.15, 37.55) radius 4.5
  circle C2 centre (22.15, 37.55) radius 5
  point P4 (22.15, 42.55)
  point P5 (22.15, 32.55)
  concentric C1 C2
  coincident C2 P4
  coincident C2 P5
  vertical L1
  dimension "d106" diameter C2 = 10
extrude "Extrusion29" add sketch "Skizze21" along normal blind 15
fillet "Abrundung7" radius 1
sketch "Skizze22" plane through (14, 0, 0) normal (-1, 0, 0) x axis (0, -1, 0)
  line L1 (22.15, 42.55) -> (22.15, 32.55)
  line L2 (19.15, 37.55) -> (22.15, 37.55)
  line L3 (19.15, 42.5259) -> (19.15, 37.55)
  line L4 (19.15, 32.3881) -> (19.15, 42.5259)
  arc A1 centre (22.15, 37.55) radius 5 clockwise from (22.15, 32.55) to (22.15, 42.55)
  point P4 (22.15, 37.55)
  point P5 (22.15, 37.55)
  point P6 (19.15, 37.55)
  coincident P4 P5
  perpendicular L1 L2
  perpendicular L2 L3
  perpendicular L2 L4
  dimension "d111" distance P5 P6 = 3
extrude "Extrusion30" cut sketch "Skizze22" profile of A1 L3 L4 against normal blind 15
delete_face "Fläche löschen2"
sketch "Skizze23" plane through (43, 0, 0) normal (1, 0, 0) x axis (0, 1, 0)
  circle C1 centre (-22.15, 37.55) radius 4.5
  circle C2 centre (-22.15, 37.55) radius 2.5
  concentric C1 C2
  dimension "d114" diameter C2 = 5
extrude "Extrusion31" cut sketch "Skizze23" profile of C2 against normal blind 12
extrude "Extrusion32" add of existing geometry blind 12
sketch "Skizze24" plane through (0, -22.15, 0) normal (0, -1, 0) x axis (1, 0, 0)
  line L1 (29, 33.05) -> (14, 33.05)
  line L2 (29, 42.05) -> (29, 33.05)
  line L3 (14, 42.05) -> (29, 42.05)
  line L4 (14, 33.05) -> (14, 42.05)
  line L5 (43, 37.55) -> (14, 37.55)
  line L6 (43, 35.55) -> (43, 37.55)
  line L7 (40, 35.55) -> (43, 35.55)
  line L8 (40, 39.55) -> (40, 35.55)
  line L9 (43, 39.55) -> (40, 39.55)
  line L10 (43, 35.55) -> (43, 39.55)
  point P6 (14, 37.55)
  point P7 (43, 37.55)
  point P8 (43, 35.55)
  point P9 (40, 35.55)
  point P11 (43, 39.55)
  midpoint L4 P6
  perpendicular L4 L5
  perpendicular L5 L6
  horizontal L7
  vertical L8
  horizontal L9
  vertical L10
  dimension "d119" distance P7 P8 = 2
  dimension "d120" distance P8 P9 = 3
  dimension "d121" distance P8 P11 = 4
extrude "Extrusion33" add sketch "Skizze24" profile of L5 L6 L7 L8 L9 L10 along normal blind 11
extrude "Extrusion34" cut of existing geometry blind 30
extrude "Extrusion35" add sketch "Skizze24" profile of L5 L6 L7 L8 L9 L10 against normal blind 7.5
extrude "Extrusion36" cut of existing geometry blind 16.5
extrude "Extrusion37" add of existing geometry blind 1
